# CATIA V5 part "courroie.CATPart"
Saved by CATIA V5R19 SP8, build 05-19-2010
Part number: courroie
Bounding box of the stored display mesh (mm): x 0 to 30, y -23.019 to 216.901, z -22.51 to 22.5
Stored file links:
  G:\EU_thinkMotion\CFAO_2010\MMS_groupe2\MMS_groupe2\A reprendre\splanchenault\Planchenault\courroie.CATPart
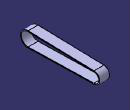
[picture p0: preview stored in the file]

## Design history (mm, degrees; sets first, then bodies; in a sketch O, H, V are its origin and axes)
Body1 (main body)
  Sketch1 on yz-plane, origin (0, 0, 0), H (0, 1, 0), V (0, 0, 1)
    point P1 (200, 0)
    point P2 (0, 22.5)
    point P3 (0, -22.5102)
    point P4 (0, 20)
    point P5 (0, -20.009)
    arc A1 centre (-0.5997, -0.0045) radius 20.0135 from (0, -20.009) to (0, 20) cw
    arc A2 centre (-0.6745, -0.0051) radius 22.5152 from (0, -22.5102) to (0, 22.5) cw
    point P8 (-10.3794, 20.3111)
    line L1 (0, 22.5) -> (200, 17.5055)
    line L2 (0, -22.5102) -> (200, -17.5055)
    arc A3 centre (199.5628, 0) radius 17.5109 from (200, 17.5055) to (200, -17.5055) cw
    line L3 (0, 20) -> (199.9376, 15.0062)
    line L4 (0, -20.009) -> (199.9375, -15.0063)
    arc A4 centre (199.562, 0) radius 15.0109 from (199.9376, 15.0062) to (199.9375, -15.0063) cw
    distance P1 V = 200
    coincidence: P1 H, P2 V, P3 V, P4 V, P5 V, A2 P8
    tangency: A3 L1, A4 L4
  Pad1: profile Sketch1, direction (1, 0, 0), length 30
